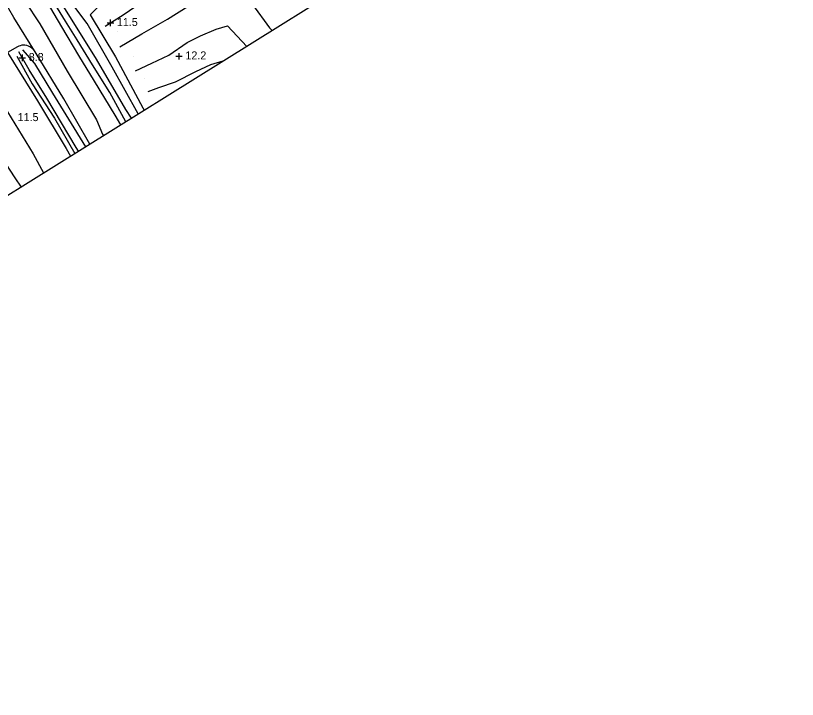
# Model space of a CAD drawing. Extents: x 2316231 to 2323598, y 363169 to 371906.
# Drawn here: x 2318819.2 to 2319307.8, y 368745.7 to 369172.9 of the extents above; entities that cross this region are included whole.
import ezdxf

# ---------------------------------------------------------------- set-up
doc = ezdxf.new("R2010")
doc.units = 0
for name, color, linetype in [('RD_DTM_BkLn1', 7, 'Continuous'), ('RD_DTM_Spot', 7, 'Continuous'), ('RD_DTM_TinHull', 7, 'Continuous'), ('RD_DTM_Void', 7, 'Continuous'), ('RD_EX_H2O', 7, 'Continuous'), ('RD_EX_Road', 7, 'Continuous')]:
    doc.layers.add(name, color=color, linetype=linetype)

msp = doc.modelspace()

# ---------------------------------------------------------------- linework, layer by layer
at = {"layer": 'RD_DTM_BkLn1'}
for points in [[(2318888.054, 369106.584), (2318878.077, 369124.886), (2318867.174, 369142.049), (2318857.671, 369157.652), (2318850.344, 369169.473), (2318839.219, 369187.556), (2318836.987, 369189.824), (2318834.702, 369193.536), (2318824.897, 369212.961), (2318824.071, 369221.691), (2318824.225, 369228.244), (2318827.955, 369233.739), (2318833.372, 369237.948), (2318842.609, 369244.322), (2318855.324, 369251.5), (2318873.684, 369263.066), (2318888.869, 369272.392), (2318898.144, 369277.023), (2318902.729, 369279.493)], [(2318895.83, 369111.431), (2318879.521, 369140.683), (2318863.991, 369167.873), (2318854.283, 369180.685), (2318844.566, 369198.808), (2318833.567, 369216.067), (2318832.378, 369223.713), (2318836.355, 369228.526), (2318841.205, 369231.628), (2318844.194, 369232.484), (2318845.974, 369234.933), (2318851.934, 369237.946), (2318852.392, 369234.279), (2318848.458, 369228.319), (2318844.896, 369229.735)], [(2318809.793, 369207.669), (2318825.043, 369181.817), (2318834.232, 369167.791), (2318851.397, 369138.228), (2318869.679, 369107.681), (2318873.44, 369098.733), (2318874.033, 369097.843)], [(2318875.168, 369166.298), (2318886.437, 369173.293), (2318898.837, 369181.799), (2318909.73, 369187.71), (2318920.136, 369193.803), (2318928.508, 369199.166), (2318942.328, 369207.712)], [(2318884.399, 369153.322), (2318898.085, 369161.403), (2318914.117, 369170.689), (2318926.98, 369178.822), (2318938.139, 369185.245), (2318945.668, 369189.132), (2318954.064, 369194.436), (2318967.296, 369179.767), (2318977.951, 369165.244), (2318979.459, 369163.565)], [(2318894.013, 369138.398), (2318904.231, 369143.095), (2318914.858, 369148.088), (2318926.311, 369156.038), (2318934.808, 369160.231), (2318944.535, 369164.489), (2318951.577, 369166.445), (2318963.599, 369153.677)], [(2318620.752, 369049.439), (2318652.447, 369068.132), (2318685.364, 369087.678), (2318724.622, 369112.217), (2318760.651, 369135.591), (2318773.455, 369145.992), (2318792.36, 369154.606), (2318800.146, 369137.114), (2318811.808, 369116.58), (2318830.247, 369086.414), (2318836.67, 369074.551)], [(2318819.945, 369147.609), (2318829.583, 369130.286), (2318843.435, 369108.762), (2318856.183, 369086.715)], [(2318823.392, 369151.554), (2318831.082, 369142.991), (2318842.217, 369124.454), (2318852.218, 369108.263), (2318862.831, 369090.86)], [(2318902.122, 369125.511), (2318908.783, 369127.911), (2318919.115, 369131.498), (2318931.718, 369137.877), (2318941.232, 369142.399), (2318948.932, 369144.534)], [(2318538.409, 368932.692), (2318550.185, 368943.632), (2318579.786, 368961.226), (2318616.719, 368981.802), (2318646.49, 369000.028), (2318681.766, 369018.726), (2318716.513, 369038.8), (2318750.35, 369060.837), (2318777.474, 369077.37), (2318803.788, 369094.217), (2318818.721, 369071.471), (2318822.562, 369065.756)]]:
    msp.add_lwpolyline(points, dxfattribs=at)
at = {"layer": 'RD_DTM_Spot'}
for p, q in [((2318883.088, 369162.783), (2318883.088, 369162.783)), ((2318892.985, 369147.177), (2318892.985, 369147.177)), ((2318899.442, 369133.535), (2318899.442, 369133.535))]:
    msp.add_line(p, q, dxfattribs=at)
at = {"layer": 'RD_DTM_TinHull'}
msp.add_lwpolyline([(2321400.963, 368599.408), (2321534.916, 368777.939), (2321271.463, 369044.178), (2321175.279, 369261.496), (2321099.267, 369551.406), (2321096.219, 369852.637), (2320858.06, 369744.011), (2320482.587, 369669.607), (2320232.924, 369604.892), (2319951.333, 369602.051), (2320092.085, 369259.27), (2319866.523, 369058.699), (2319771.694, 369171.639), (2319557.442, 369523.873), (2318254.179, 368711.432)], dxfattribs=at)
at = {"layer": 'RD_DTM_Void'}
for p, q in [((2318876.49, 369168.36), (2318880.49, 369168.36)), ((2318878.49, 369166.36), (2318878.49, 369170.36)), ((2318823.408, 369144.503), (2318823.408, 369148.503)), ((2318919.324, 369147.517), (2318923.324, 369147.517)), ((2318921.324, 369145.517), (2318921.324, 369149.517)), ((2318821.408, 369146.503), (2318825.408, 369146.503))]:
    msp.add_line(p, q, dxfattribs=at)
at = {"layer": 'RD_EX_H2O'}
for points in [[(2318891.575, 369108.778), (2318888.072, 369114.257), (2318869.819, 369145.664), (2318849.245, 369178.371), (2318828.542, 369216.093)], [(2318858.489, 369088.153), (2318857.043, 369090.547), (2318838.775, 369121.392), (2318827.73, 369138.962), (2318821.225, 369150.312)]]:
    msp.add_lwpolyline(points, dxfattribs=at)
at = {"layer": 'RD_EX_Road'}
for points in [[(2318901.349, 369282.568), (2318906.822, 369281.382), (2318915.526, 369272.765), (2318930.488, 369253.313), (2318946.528, 369230.095), (2318951.58, 369214.706), (2318952.136, 369209.26), (2318949.71, 369208.64), (2318944.763, 369216.783), (2318941.595, 369220.357), (2318921.268, 369209.41), (2318891.85, 369194.727), (2318870.143, 369177.796), (2318865.728, 369173.402), (2318881.656, 369147.07), (2318898.714, 369115.311), (2318899.605, 369113.784)], [(2318865.563, 369092.563), (2318849.372, 369120.787), (2318831.951, 369149.301), (2318818.114, 369171.6), (2318805.302, 369193.512), (2318796.542, 369207.536), (2318788.019, 369221.081), (2318779.717, 369233.587), (2318777.591, 369237.848)], [(2318824.67, 369206.087), (2318828.367, 369198.607), (2318836.118, 369185.829), (2318847.914, 369165.857), (2318858.408, 369148.051), (2318868.207, 369132.004), (2318881.166, 369110.605), (2318884.834, 369104.576)], [(2318820.357, 369153.349), (2318814.012, 369149.825), (2318832.952, 369119.632), (2318850.677, 369089.769), (2318853.516, 369085.053)]]:
    msp.add_lwpolyline(points, dxfattribs=at)
msp.add_spline([(2318830.553, 369151.553), (2318828.164, 369153.272), (2318823.921, 369154.488), (2318820.357, 369153.349)], degree=3, dxfattribs=at)

# ---------------------------------------------------------------- texts
at = {"layer": 'RD_DTM_Void'}
for s, p in [('11.5', (2318882.49, 369166.36)), ('8.8', (2318827.408, 369144.503)), ('12.2', (2318925.324, 369145.517)), ('11.5', (2318820.464, 369106.963))]:
    msp.add_text(s, height=5, dxfattribs=at).set_placement(p)

doc.saveas('drawing.dxf')
